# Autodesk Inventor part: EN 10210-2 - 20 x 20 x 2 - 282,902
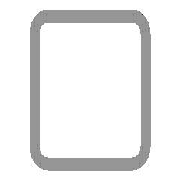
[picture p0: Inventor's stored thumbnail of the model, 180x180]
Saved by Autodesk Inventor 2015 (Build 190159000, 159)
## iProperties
Created: 2014-02
Part Number: EN 10210-2 - 20 x 20 x 2 - 282,902
Material: Steel, Mild
Description: Tube
Document SubType Name: Modeling
Standard: DIN
Designer: TREINA6
Standard Revision: 1997
Standards Organization: DIN
Language: en-US
Size Designation: 20 x 20 x 2
Categories: <MemberInstance><Categories><Category DisplayName="Structural Shapes" InternalName="089c4875-fa83-4c05-b084-43b9cc11f5ed" Mnemonic="GRDR"><CategoryParameter Dis
Stock Number: 20 x 20 x 2
Density: 7.85 g/cm^3
Appearance: Semi-Polished
_CCFamilyMember: 1
_CCFamilyDisplayName: DIN EN 10210-2 (Square) - Tube
_FrameMemberDoc: Frame Member File
_Version: 15.0.0
_GetPNFromCC: 1
G_L: 282,902 mm
G_W: 20,000 mm
G_H: 20,000 mm
IsCustomPart: 1
Author: TREINA6
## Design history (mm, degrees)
node "Start plane"
node "End plane"
sketch "Sketch"
  geometry: L1 (-10, -7)-(-10, 7); L2 (-7, 10)-(7, 10); L3 (10, 7)-(10, -7); L4 (7, -10)-(-7, -10); L5 (-7, 8)-(7, 8); L6 (8, 7)-(8, -7); L7 (7, -8)-(-7, -8); L8 (-8, -7)-(-8, 7); L9 (0, 14.87)-(0, -14.87) reference; L10 (-14.87, 0)-(14.87, 0) reference; A1 r 3 centre (-7, -7) between (-10, -7) and (-7, -10); A2 r 3 centre (-7, 7) between (-7, 10) and (-10, 7); A3 r 3 centre (7, 7) between (10, 7) and (7, 10); A4 r 3 centre (7, -7) between (7, -10) and (10, -7); A5 r 1 centre (-7, 7) between (-7, 8) and (-8, 7); A6 r 1 centre (7, 7) between (8, 7) and (7, 8); A7 r 1 centre (7, -7) between (7, -8) and (8, -7); A8 r 1 centre (-7, -7) between (-8, -7) and (-7, -8)
  constraints: 16 end point, 16 point on circle, 8 centre point, 8 tangent, 4 parallel, 3 equal radius, 2 perpendicular, 7 other
  dimensions: "d7" = 3 radius of A1 (= G_IR); "d10" = 20 distance between parallel lines of L2 L4 (= G_H); "d11" = 20 distance between parallel lines of L1 L3 (= G_W); "d12" = 2 distance between parallel lines of L3 L6 (= G_T); "d15" = 10 distance between parallel lines of L2 L10 (= 0.5 x d10); "d16" = 10 distance between parallel lines of L9 L3 (= 0.5 x d11)
extrude "Body" new body sketch "Sketch" stored distance "d3" = 282.90163 (= G_L); taper "d4" = 0 deg
node "Driven Length"
  sketch "Sketch3"
    geometry: L1 (0, 0)-(10, 0) reference
    constraints: 2 end point, 1 horizontal
  workplane "Work Plane3"
  sketch "Sketch4"
    geometry: L1 (-2, 0)-(12, 0) reference; L2 (-2, 282.902)-(12, 282.902) reference
    dimensions: "d18" = 282.90163 distance between parallel lines of L1 L2 (derived)
body "Solid1"
other parameters: "G_W" = 20 [user parameter; used in 1 equation term], "G_H" = 20 [user parameter; used in 1 equation term], "G_T" = 2 [user parameter; used in 1 equation term], "G_IR" = 3 [user parameter; used in 1 equation term], "G_L" = 282.90163 (= d18) [user parameter; used in 1 equation term], "G_OFFSET_START" = 0 [user parameter; used in 1 equation term], "G_OFFSET_END" = 0 [user parameter; used in 1 equation term], "d13" = 0 (computed from G_OFFSET_START), "d14" = 282.90163 (= G_OFFSET_END + B_L), "B_L" = 282.90163 [user parameter; used in 1 equation term], "d17" = 90 deg
